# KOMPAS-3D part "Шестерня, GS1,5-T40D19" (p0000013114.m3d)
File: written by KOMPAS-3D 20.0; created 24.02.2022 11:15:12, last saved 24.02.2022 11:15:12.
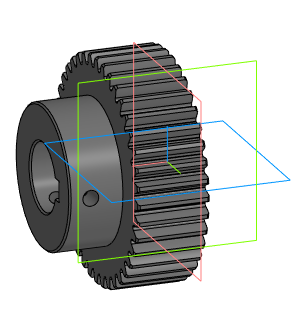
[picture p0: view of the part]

Document properties: Автор: 1; Полное имя файла: \\dc2\Design\Чепков\3D модели комплектующих\3D\p0000013114.m3d

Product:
- Part/product: Шестерня  | designation GS1,5-T40D19
    Комментарий: Модуль генерации 3D-моделей программы "Валы и механические передачи 2D"

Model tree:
1. Операция без истории:1  (labels: GS1,5-T40D19)

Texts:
  Модуль генерации 3D-моделей программы "Валы и механические передачи 2D"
